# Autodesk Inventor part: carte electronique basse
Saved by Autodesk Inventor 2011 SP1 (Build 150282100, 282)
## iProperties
Created: 2010-12
Part Number: carte electronique basse
Document SubType Name: Modeling
Designer: eric
Density: 1 g/cm^3
Author: eric
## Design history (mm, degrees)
feature "Base1"
node "Solide1"
node "Corps solides"
node "Corps surfaciques"
